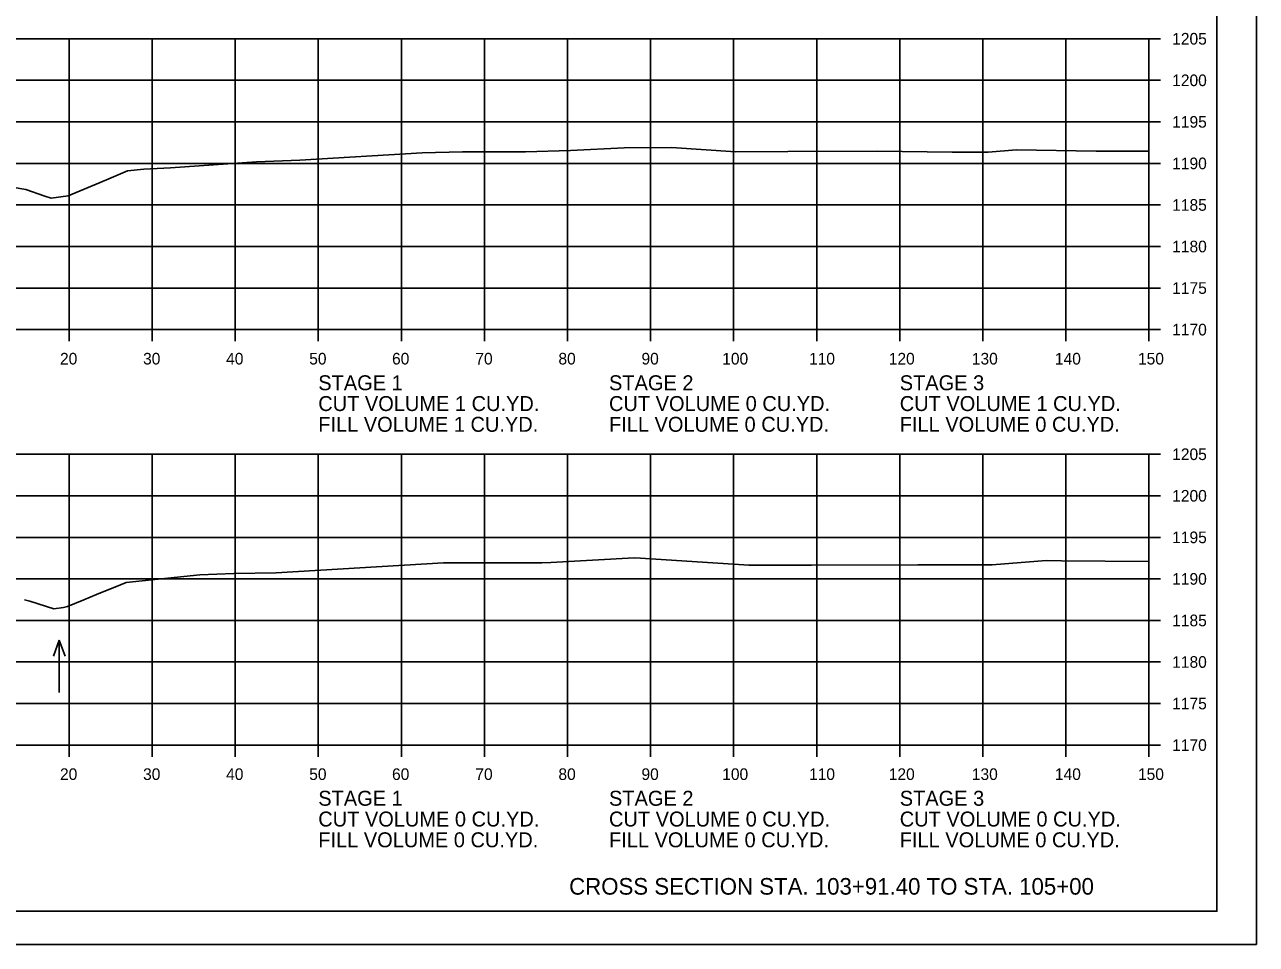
# Model space of a CAD drawing. Extents: x 1368971 to 1374497, y 378717 to 381839.
# Drawn here: x 1371067.4 to 1371215.6, y 378717.1 to 378827.8 of the extents above; entities that cross this region are included whole.
import ezdxf

# ---------------------------------------------------------------- set-up
doc = ezdxf.new("R2010")
doc.units = 0
for name, color, linetype in [('R_Axis', 7, 'Continuous'), ('R_Axis Annot', 7, 'Continuous'), ('R_Border', 7, 'Continuous'), ('R_Draft', 7, 'Continuous'), ('R_Exist Surface', 7, 'Continuous'), ('R_Grid', 7, 'Continuous'), ('R_No Plot', 7, 'Continuous'), ('R_Water Annot', 7, 'Continuous')]:
    doc.layers.add(name, color=color, linetype=linetype)

msp = doc.modelspace()

# ---------------------------------------------------------------- linework, layer by layer
at = {"layer": 'R_Axis'}
for p, q in [((1371202.71, 378791.06), (1371202.71, 378826.06)), ((1371204.11, 378826.06), (1371202.71, 378826.06)), ((1371204.11, 378821.06), (1371202.71, 378821.06)), ((1371204.11, 378816.06), (1371202.71, 378816.06)), ((1371204.11, 378811.06), (1371202.71, 378811.06)), ((1371204.11, 378806.06), (1371202.71, 378806.06)), ((1371204.11, 378801.06), (1371202.71, 378801.06)), ((1371204.11, 378796.06), (1371202.71, 378796.06)), ((1370902.71, 378791.06), (1371202.71, 378791.06)), ((1371072.71, 378789.66), (1371072.71, 378791.06)), ((1371082.71, 378789.66), (1371082.71, 378791.06)), ((1371092.71, 378789.66), (1371092.71, 378791.06)), ((1371102.71, 378789.66), (1371102.71, 378791.06)), ((1371112.71, 378789.66), (1371112.71, 378791.06)), ((1371122.71, 378789.66), (1371122.71, 378791.06)), ((1371132.71, 378789.66), (1371132.71, 378791.06)), ((1371142.71, 378789.66), (1371142.71, 378791.06)), ((1371152.71, 378789.66), (1371152.71, 378791.06)), ((1371162.71, 378789.66), (1371162.71, 378791.06)), ((1371172.71, 378789.66), (1371172.71, 378791.06)), ((1371182.71, 378789.66), (1371182.71, 378791.06)), ((1371192.71, 378789.66), (1371192.71, 378791.06)), ((1371202.71, 378789.66), (1371202.71, 378791.06)), ((1371204.11, 378791.06), (1371202.71, 378791.06)), ((1371202.71, 378741.06), (1371202.71, 378776.06)), ((1371204.11, 378776.06), (1371202.71, 378776.06)), ((1371204.11, 378771.06), (1371202.71, 378771.06)), ((1371204.11, 378766.06), (1371202.71, 378766.06)), ((1371204.11, 378761.06), (1371202.71, 378761.06)), ((1371204.11, 378756.06), (1371202.71, 378756.06)), ((1371204.11, 378751.06), (1371202.71, 378751.06)), ((1371204.11, 378746.06), (1371202.71, 378746.06)), ((1370902.71, 378741.06), (1371202.71, 378741.06)), ((1371072.71, 378739.66), (1371072.71, 378741.06)), ((1371082.71, 378739.66), (1371082.71, 378741.06)), ((1371092.71, 378739.66), (1371092.71, 378741.06)), ((1371102.71, 378739.66), (1371102.71, 378741.06)), ((1371112.71, 378739.66), (1371112.71, 378741.06)), ((1371122.71, 378739.66), (1371122.71, 378741.06)), ((1371132.71, 378739.66), (1371132.71, 378741.06)), ((1371142.71, 378739.66), (1371142.71, 378741.06)), ((1371152.71, 378739.66), (1371152.71, 378741.06)), ((1371162.71, 378739.66), (1371162.71, 378741.06)), ((1371172.71, 378739.66), (1371172.71, 378741.06)), ((1371182.71, 378739.66), (1371182.71, 378741.06)), ((1371192.71, 378739.66), (1371192.71, 378741.06)), ((1371202.71, 378739.66), (1371202.71, 378741.06)), ((1371204.11, 378741.06), (1371202.71, 378741.06))]:
    msp.add_line(p, q, dxfattribs=at)
at = {"layer": 'R_Border'}
for q in [(1371210.89, 378926.52), (1370894.71, 378721.06)]:
    msp.add_line((1371210.89, 378721.06), q, dxfattribs=at)
at = {"layer": 'R_Exist Surface'}
for points in [[(1371065.85, 378808.21), (1371067.5, 378807.91), (1371069.78, 378807.12), (1371070.54, 378806.88), (1371072.6, 378807.14), (1371072.6, 378807.14), (1371072.6, 378807.15), (1371075.97, 378808.57), (1371077.23, 378809.08), (1371079.73, 378810.18), (1371081.73, 378810.38), (1371084.92, 378810.53), (1371095.28, 378811.26), (1371100.49, 378811.47), (1371115.23, 378812.33), (1371120.08, 378812.47), (1371127.66, 378812.44), (1371133.09, 378812.6), (1371139.53, 378812.94), (1371145.22, 378812.97), (1371152.96, 378812.46), (1371159.22, 378812.49), (1371170, 378812.53), (1371179.04, 378812.42), (1371183.34, 378812.42), (1371186.78, 378812.68), (1371196.37, 378812.55), (1371202.71, 378812.52)], [(1371067.33, 378758.55), (1371067.98, 378758.37), (1371070.86, 378757.46), (1371072.04, 378757.61), (1371072.53, 378757.72), (1371074.5, 378758.53), (1371076.02, 378759.17), (1371078.92, 378760.35), (1371079.57, 378760.63), (1371088.46, 378761.53), (1371092.54, 378761.72), (1371097.66, 378761.8), (1371117.8, 378762.98), (1371118.62, 378762.99), (1371129.61, 378762.98), (1371130.71, 378763.04), (1371140.72, 378763.58), (1371141.52, 378763.56), (1371154.55, 378762.7), (1371154.76, 378762.7), (1371162.09, 378762.72), (1371174.88, 378762.77), (1371175.66, 378762.76), (1371183.82, 378762.77), (1371190.34, 378763.26), (1371192.19, 378763.23), (1371202.71, 378763.17)]]:
    msp.add_lwpolyline(points, dxfattribs=at)
at = {"layer": 'R_Grid'}
for p, q in [((1370902.71, 378826.06), (1371202.71, 378826.06)), ((1371072.71, 378791.06), (1371072.71, 378826.06)), ((1371082.71, 378791.06), (1371082.71, 378826.06)), ((1371092.71, 378791.06), (1371092.71, 378826.06)), ((1371102.71, 378791.06), (1371102.71, 378826.06)), ((1371112.71, 378791.06), (1371112.71, 378826.06)), ((1371122.71, 378791.06), (1371122.71, 378826.06)), ((1371132.71, 378791.06), (1371132.71, 378826.06)), ((1371142.71, 378791.06), (1371142.71, 378826.06)), ((1371152.71, 378791.06), (1371152.71, 378826.06)), ((1371162.71, 378791.06), (1371162.71, 378826.06)), ((1371172.71, 378791.06), (1371172.71, 378826.06)), ((1371182.71, 378791.06), (1371182.71, 378826.06)), ((1371192.71, 378791.06), (1371192.71, 378826.06)), ((1371202.71, 378791.06), (1371202.71, 378826.06)), ((1370902.71, 378821.06), (1371202.71, 378821.06)), ((1370902.71, 378816.06), (1371202.71, 378816.06)), ((1370902.71, 378811.06), (1371202.71, 378811.06)), ((1370902.71, 378806.06), (1371202.71, 378806.06)), ((1370902.71, 378801.06), (1371202.71, 378801.06)), ((1370902.71, 378796.06), (1371202.71, 378796.06)), ((1370902.71, 378791.06), (1371202.71, 378791.06)), ((1370902.71, 378776.06), (1371202.71, 378776.06)), ((1371072.71, 378741.06), (1371072.71, 378776.06)), ((1371082.71, 378741.06), (1371082.71, 378776.06)), ((1371092.71, 378741.06), (1371092.71, 378776.06)), ((1371102.71, 378741.06), (1371102.71, 378776.06)), ((1371112.71, 378741.06), (1371112.71, 378776.06)), ((1371122.71, 378741.06), (1371122.71, 378776.06)), ((1371132.71, 378741.06), (1371132.71, 378776.06)), ((1371142.71, 378741.06), (1371142.71, 378776.06)), ((1371152.71, 378741.06), (1371152.71, 378776.06)), ((1371162.71, 378741.06), (1371162.71, 378776.06)), ((1371172.71, 378741.06), (1371172.71, 378776.06)), ((1371182.71, 378741.06), (1371182.71, 378776.06)), ((1371192.71, 378741.06), (1371192.71, 378776.06)), ((1371202.71, 378741.06), (1371202.71, 378776.06)), ((1370902.71, 378771.06), (1371202.71, 378771.06)), ((1370902.71, 378766.06), (1371202.71, 378766.06)), ((1370902.71, 378761.06), (1371202.71, 378761.06)), ((1370902.71, 378756.06), (1371202.71, 378756.06)), ((1370902.71, 378751.06), (1371202.71, 378751.06)), ((1370902.71, 378746.06), (1371202.71, 378746.06)), ((1370902.71, 378741.06), (1371202.71, 378741.06))]:
    msp.add_line(p, q, dxfattribs=at)
at = {"layer": 'R_No Plot'}
msp.add_line((1370882.31, 378717.08), (1371215.64, 378717.08), dxfattribs=at)
for points in [[(1370882.3, 378930.42), (1371215.64, 378930.42), (1371215.64, 378717.08), (1370882.3, 378717.08)], [(1371128.63, 378926.52), (1371128.63, 378916.64), (1371164.36, 378916.64), (1371164.36, 378913.72), (1371187.56, 378913.72), (1371187.56, 378889.39), (1371210.89, 378889.39), (1371210.89, 378721.06), (1370894.71, 378721.06), (1370894.71, 378926.52)]]:
    msp.add_lwpolyline(points, close=True, dxfattribs=at)
at = {"layer": 'R_Water Annot'}
for p, q in [((1371071.53, 378753.68), (1371070.83, 378751.76)), ((1371071.53, 378747.4), (1371071.53, 378753.68)), ((1371071.53, 378753.68), (1371072.23, 378751.76))]:
    msp.add_line(p, q, dxfattribs=at)

# ---------------------------------------------------------------- texts
at = {"layer": 'R_Axis Annot'}
for s, height, p in [('1205', 1.4, (1371205.51, 378825.36)), ('1200', 1.4, (1371205.51, 378820.36)), ('1195', 1.4, (1371205.51, 378815.36)), ('1190', 1.4, (1371205.51, 378810.36)), ('1185', 1.4, (1371205.51, 378805.36)), ('1180', 1.4, (1371205.51, 378800.36)), ('1175', 1.4, (1371205.51, 378795.36)), ('1170', 1.4, (1371205.51, 378790.36)), ('20', 1.4, (1371071.62, 378786.86)), ('30', 1.4, (1371081.62, 378786.86)), ('40', 1.4, (1371091.62, 378786.86)), ('50', 1.4, (1371101.62, 378786.86)), ('60', 1.4, (1371111.59, 378786.86)), ('70', 1.4, (1371121.62, 378786.86)), ('80', 1.4, (1371131.62, 378786.86)), ('90', 1.4, (1371141.62, 378786.86)), ('100', 1.4, (1371151.34, 378786.86)), ('110', 1.4, (1371161.79, 378786.86)), ('120', 1.4, (1371171.39, 378786.86)), ('130', 1.4, (1371181.39, 378786.86)), ('140', 1.4, (1371191.39, 378786.86)), ('150', 1.4, (1371201.39, 378786.86)), ('STAGE 1', 1.8, (1371102.71, 378783.76)), ('STAGE 2', 1.8, (1371137.71, 378783.76)), ('STAGE 3', 1.8, (1371172.71, 378783.76)), ('CUT VOLUME 1 CU.YD.', 1.8, (1371102.71, 378781.26)), ('CUT VOLUME 0 CU.YD.', 1.8, (1371137.71, 378781.26)), ('CUT VOLUME 1 CU.YD.', 1.8, (1371172.71, 378781.26)), ('FILL VOLUME 1 CU.YD.', 1.8, (1371102.71, 378778.76)), ('FILL VOLUME 0 CU.YD.', 1.8, (1371137.71, 378778.76)), ('FILL VOLUME 0 CU.YD.', 1.8, (1371172.71, 378778.76)), ('1205', 1.4, (1371205.51, 378775.36)), ('1200', 1.4, (1371205.51, 378770.36)), ('1195', 1.4, (1371205.51, 378765.36)), ('1190', 1.4, (1371205.51, 378760.36)), ('1185', 1.4, (1371205.51, 378755.36)), ('1180', 1.4, (1371205.51, 378750.36)), ('1175', 1.4, (1371205.51, 378745.36)), ('1170', 1.4, (1371205.51, 378740.36)), ('20', 1.4, (1371071.62, 378736.86)), ('30', 1.4, (1371081.62, 378736.86)), ('40', 1.4, (1371091.62, 378736.86)), ('50', 1.4, (1371101.62, 378736.86)), ('60', 1.4, (1371111.59, 378736.86)), ('70', 1.4, (1371121.62, 378736.86)), ('80', 1.4, (1371131.62, 378736.86)), ('90', 1.4, (1371141.62, 378736.86)), ('100', 1.4, (1371151.34, 378736.86)), ('110', 1.4, (1371161.79, 378736.86)), ('120', 1.4, (1371171.39, 378736.86)), ('130', 1.4, (1371181.39, 378736.86)), ('140', 1.4, (1371191.39, 378736.86)), ('150', 1.4, (1371201.39, 378736.86)), ('STAGE 1', 1.8, (1371102.71, 378733.76)), ('STAGE 2', 1.8, (1371137.71, 378733.76)), ('STAGE 3', 1.8, (1371172.71, 378733.76)), ('CUT VOLUME 0 CU.YD.', 1.8, (1371102.71, 378731.26)), ('CUT VOLUME 0 CU.YD.', 1.8, (1371137.71, 378731.26)), ('CUT VOLUME 0 CU.YD.', 1.8, (1371172.71, 378731.26)), ('FILL VOLUME 0 CU.YD.', 1.8, (1371102.71, 378728.76)), ('FILL VOLUME 0 CU.YD.', 1.8, (1371137.71, 378728.76)), ('FILL VOLUME 0 CU.YD.', 1.8, (1371172.71, 378728.76))]:
    msp.add_text(s, height=height, dxfattribs=at).set_placement(p)
at = {"layer": 'R_Draft'}
msp.add_text('CROSS SECTION STA. 103+91.40 TO STA. 105+00', height=2, dxfattribs=at).set_placement((1371132.91, 378723.06))

doc.saveas('drawing.dxf')
